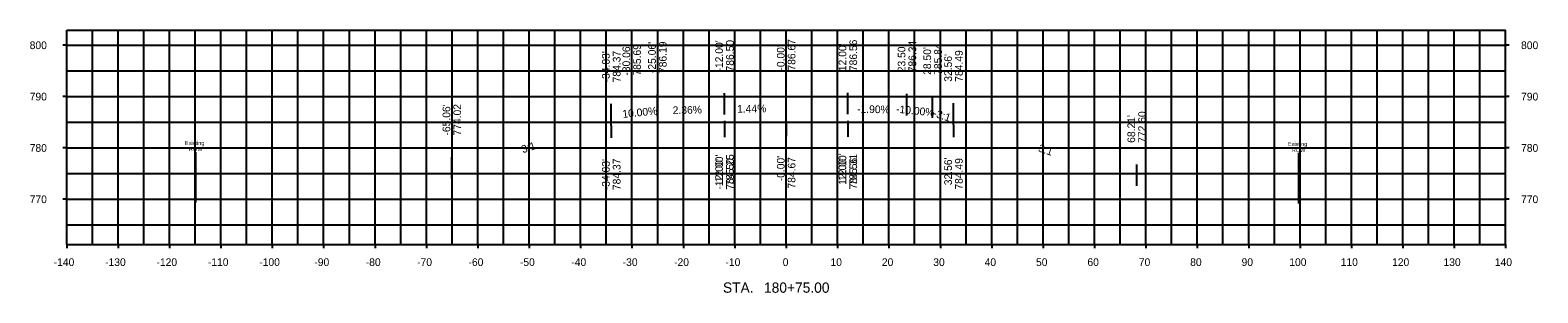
# Model space of a CAD drawing. Extents: x -147 to 146, y 752 to 803.
import ezdxf

# ---------------------------------------------------------------- set-up
doc = ezdxf.new("R2010")
doc.units = 0
for name, color, linetype in [('Default', 7, 'Continuous'), ('ROW', 7, 'Continuous'), ('SheetBorder', 7, 'Continuous'), ('SheetGridMajor', 7, 'Continuous'), ('SheetGridMinor', 7, 'Continuous'), ('Text', 7, 'Continuous')]:
    doc.layers.add(name, color=color, linetype=linetype)

msp = doc.modelspace()

# ---------------------------------------------------------------- linework, layer by layer
at = {"layer": 'ROW'}
for p, q in [((-114.91, 779.21), (-114.91, 769.37)), ((99.7, 779.03), (99.7, 769.18))]:
    msp.add_line(p, q, dxfattribs=at)
at = {"layer": 'SheetBorder'}
for p, q in [((-140, 802.95), (140, 802.95)), ((-140, 761.21), (-140, 802.95)), ((140, 761.21), (140, 802.95)), ((-140, 761.21), (140, 761.21))]:
    msp.add_line(p, q, dxfattribs=at)
at = {"layer": 'SheetGridMajor'}
for p, q in [((-130, 761.21), (-130, 802.95)), ((-120, 761.21), (-120, 802.95)), ((-110, 761.21), (-110, 802.95)), ((-100, 761.21), (-100, 802.95)), ((-90, 761.21), (-90, 802.95)), ((-80, 761.21), (-80, 802.95)), ((-70, 761.21), (-70, 802.95)), ((-60, 761.21), (-60, 802.95)), ((-50, 761.21), (-50, 802.95)), ((-40, 761.21), (-40, 802.95)), ((-30, 761.21), (-30, 802.95)), ((-20, 761.21), (-20, 802.95)), ((-10, 761.21), (-10, 802.95)), ((0, 761.21), (0, 802.95)), ((10, 761.21), (10, 802.95)), ((20, 761.21), (20, 802.95)), ((30, 761.21), (30, 802.95)), ((40, 761.21), (40, 802.95)), ((50, 761.21), (50, 802.95)), ((60, 761.21), (60, 802.95)), ((70, 761.21), (70, 802.95)), ((80, 761.21), (80, 802.95)), ((90, 761.21), (90, 802.95)), ((100, 761.21), (100, 802.95)), ((110, 761.21), (110, 802.95)), ((120, 761.21), (120, 802.95)), ((130, 761.21), (130, 802.95)), ((-140, 800), (-140.72, 800)), ((-140, 800), (140, 800)), ((140.72, 800), (140, 800)), ((-140, 790), (-140.72, 790)), ((-140, 790), (140, 790)), ((140.72, 790), (140, 790)), ((-140, 780), (-140.72, 780)), ((-140, 780), (140, 780)), ((140.72, 780), (140, 780)), ((-140, 770), (-140.72, 770)), ((-140, 770), (140, 770)), ((140.72, 770), (140, 770)), ((-140, 761.21), (-140, 760.49)), ((-130, 761.21), (-130, 760.49)), ((-120, 761.21), (-120, 760.49)), ((-110, 761.21), (-110, 760.49)), ((-100, 761.21), (-100, 760.49)), ((-90, 761.21), (-90, 760.49)), ((-80, 761.21), (-80, 760.49)), ((-70, 761.21), (-70, 760.49)), ((-60, 761.21), (-60, 760.49)), ((-50, 761.21), (-50, 760.49)), ((-40, 761.21), (-40, 760.49)), ((-30, 761.21), (-30, 760.49)), ((-20, 761.21), (-20, 760.49)), ((-10, 761.21), (-10, 760.49)), ((0, 761.21), (0, 760.49)), ((10, 761.21), (10, 760.49)), ((20, 761.21), (20, 760.49)), ((30, 761.21), (30, 760.49)), ((40, 761.21), (40, 760.49)), ((50, 761.21), (50, 760.49)), ((60, 761.21), (60, 760.49)), ((70, 761.21), (70, 760.49)), ((80, 761.21), (80, 760.49)), ((90, 761.21), (90, 760.49)), ((100, 761.21), (100, 760.49)), ((110, 761.21), (110, 760.49)), ((120, 761.21), (120, 760.49)), ((130, 761.21), (130, 760.49)), ((140, 761.21), (140, 760.49))]:
    msp.add_line(p, q, dxfattribs=at)
at = {"layer": 'SheetGridMinor'}
for p, q in [((-135, 761.21), (-135, 802.95)), ((-125, 761.21), (-125, 802.95)), ((-115, 761.21), (-115, 802.95)), ((-105, 761.21), (-105, 802.95)), ((-95, 761.21), (-95, 802.95)), ((-85, 761.21), (-85, 802.95)), ((-75, 761.21), (-75, 802.95)), ((-65, 761.21), (-65, 802.95)), ((-55, 761.21), (-55, 802.95)), ((-45, 761.21), (-45, 802.95)), ((-35, 761.21), (-35, 802.95)), ((-25, 761.21), (-25, 802.95)), ((-15, 761.21), (-15, 802.95)), ((-5, 761.21), (-5, 802.95)), ((5, 761.21), (5, 802.95)), ((15, 761.21), (15, 802.95)), ((25, 761.21), (25, 802.95)), ((35, 761.21), (35, 802.95)), ((45, 761.21), (45, 802.95)), ((55, 761.21), (55, 802.95)), ((65, 761.21), (65, 802.95)), ((75, 761.21), (75, 802.95)), ((85, 761.21), (85, 802.95)), ((95, 761.21), (95, 802.95)), ((105, 761.21), (105, 802.95)), ((115, 761.21), (115, 802.95)), ((125, 761.21), (125, 802.95)), ((135, 761.21), (135, 802.95)), ((-140, 795), (140, 795)), ((-140, 785), (140, 785)), ((-140, 775), (140, 775)), ((-140, 765), (140, 765))]:
    msp.add_line(p, q, dxfattribs=at)
at = {"layer": 'Text'}
for p, q in [((-30.06, 785.69), (-30.06, 789.89)), ((-25.06, 786.19), (-25.06, 790.39)), ((-12, 786.5), (-12, 790.7)), ((-12, 786.5), (-12, 790.7)), ((0, 786.67), (0, 790.87)), ((12, 786.56), (12, 790.76)), ((12, 786.56), (12, 790.76)), ((23.5, 786.34), (23.5, 790.54)), ((28.5, 785.84), (28.5, 790.04)), ((-34.03, 784.37), (-34.03, 788.57)), ((32.56, 784.49), (32.56, 788.69)), ((32.56, 784.49), (32.56, 788.69)), ((-34.03, 784.37), (-34.03, 781.97)), ((-12, 785.25), (-12, 782.85)), ((-12, 784.5), (-12, 782.1)), ((0, 784.67), (0, 782.27)), ((12, 785.31), (12, 782.91)), ((12, 784.56), (12, 782.16)), ((32.56, 784.49), (32.56, 782.09)), ((-65.06, 774.02), (-65.06, 778.22)), ((68.21, 772.6), (68.21, 776.8))]:
    msp.add_line(p, q, dxfattribs=at)

# ---------------------------------------------------------------- texts
at = {"layer": 'Default'}
for s, height, p in [('800', 1.5, (-147.2, 799.25)), ('800', 1.5, (143, 799.25)), ('790', 1.5, (-147.2, 789.25)), ('790', 1.5, (143, 789.25)), ('780', 1.5, (-147.2, 779.25)), ('780', 1.5, (143, 779.25)), ('770', 1.5, (-147.2, 769.25)), ('770', 1.5, (143, 769.25)), ('-140', 1.5, (-142.53, 757.01)), ('-130', 1.5, (-132.53, 757.01)), ('-120', 1.5, (-122.53, 757.01)), ('-110', 1.5, (-112.53, 757.01)), ('-100', 1.5, (-102.53, 757.01)), ('-90', 1.5, (-91.81, 757.01)), ('-80', 1.5, (-81.81, 757.01)), ('-70', 1.5, (-71.81, 757.01)), ('-60', 1.5, (-61.81, 757.01)), ('-50', 1.5, (-51.81, 757.01)), ('-40', 1.5, (-41.81, 757.01)), ('-30', 1.5, (-31.81, 757.01)), ('-20', 1.5, (-21.81, 757.01)), ('-10', 1.5, (-11.81, 757.01)), ('0', 1.5, (-0.67, 757.01)), ('10', 1.5, (8.62, 757.01)), ('20', 1.5, (18.62, 757.01)), ('30', 1.5, (28.62, 757.01)), ('40', 1.5, (38.62, 757.01)), ('50', 1.5, (48.62, 757.01)), ('60', 1.5, (58.62, 757.01)), ('70', 1.5, (68.62, 757.01)), ('80', 1.5, (78.62, 757.01)), ('90', 1.5, (88.62, 757.01)), ('100', 1.5, (97.9, 757.01)), ('110', 1.5, (107.9, 757.01)), ('120', 1.5, (117.9, 757.01)), ('130', 1.5, (127.9, 757.01)), ('140', 1.5, (137.9, 757.01)), ('STA.', 2.004, (-12.3, 751.8)), ('180+75.00', 2.004, (-4.31, 751.8))]:
    msp.add_text(s, height=height, dxfattribs=at).set_placement(p)
at = {"layer": 'ROW'}
for s, p in [('Existing', (-117, 780.56)), ('Existing', (97.61, 780.38)), ('ROW', (-116.22, 779.38)), ('ROW', (98.39, 779.2))]:
    msp.add_text(s, height=0.787, dxfattribs=at).set_placement(p)
at = {"layer": 'Text'}
for s, rotation, p in [('786.50', 90, (-10.2, 794.9)), ('786.50', 90, (-10.2, 794.9)), ('786.67', 90, (1.8, 795.07)), ('786.56', 90, (13.8, 794.96)), ('786.56', 90, (13.8, 794.96)), ("-34.03'", 90, (-34.33, 792.77)), ('784.37', 90, (-32.23, 792.77)), ("-30.06'", 90, (-30.36, 794.09)), ('785.69', 90, (-28.26, 794.09)), ("-25.06'", 90, (-25.36, 794.59)), ('786.19', 90, (-23.26, 794.59)), ("-12.00'", 90, (-12.3, 794.9)), ("-12.00'", 90, (-12.3, 794.9)), ("-0.00'", 90, (-0.3, 795.07)), ("12.00'", 90, (11.7, 794.96)), ("12.00'", 90, (11.7, 794.96)), ("23.50'", 90, (23.2, 794.74)), ('786.34', 90, (25.3, 794.74)), ("28.50'", 90, (28.2, 794.24)), ('785.84', 90, (30.3, 794.24)), ("32.56'", 90, (32.26, 792.89)), ("32.56'", 90, (32.26, 792.89)), ('784.49', 90, (34.36, 792.89)), ('784.49', 90, (34.36, 792.89)), ("-65.06'", 90, (-65.36, 782.42)), ('774.02', 90, (-63.26, 782.42)), ('10.00%', 5.7106, (-31.79, 785.85)), ('2.36%', 1.3508, (-22.07, 786.59)), ('1.44%', 0.8253, (-9.54, 786.86)), ('-1.90%', 358.909, (13.79, 786.85)), ('-10.00%', 354.2894, (21.34, 786.88)), ('-3:1', 341.5668, (28.45, 786.19)), ("68.21'", 90, (67.91, 781)), ('772.60', 90, (70.01, 781)), ('3:1', 18.4332, (-51.23, 778.96)), ('-3:1', 341.5668, (48.31, 779.57)), ("-34.03'", 90, (-34.33, 771.77)), ('784.37', 90, (-32.23, 771.79)), ("-12.00'", 90, (-12.3, 772.65)), ("-12.00'", 90, (-12.3, 771.9)), ('785.25', 90, (-10.2, 772.65)), ('784.50', 90, (-10.2, 771.85)), ("-0.00'", 90, (-0.3, 773.51)), ('784.67', 90, (1.8, 772.09)), ("12.00'", 90, (11.7, 773.56)), ("12.00'", 90, (11.7, 772.82)), ('785.31', 90, (13.8, 772.71)), ('784.56', 90, (13.8, 771.93)), ("32.56'", 90, (32.26, 772.74)), ('784.49', 90, (34.36, 771.88))]:
    msp.add_text(s, height=1.5, rotation=rotation, dxfattribs=at).set_placement(p)

doc.saveas('drawing.dxf')
